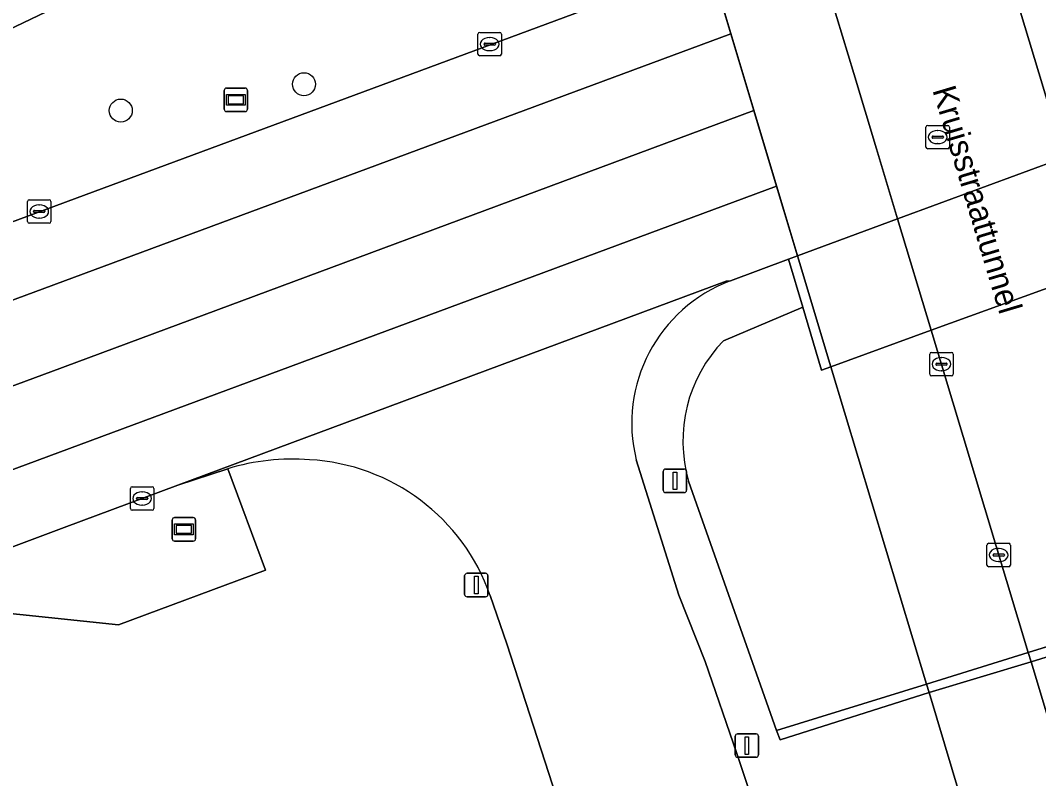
# Model space of a CAD drawing. Extents: x 160806 to 161707, y 383696 to 384148.
# Drawn here: x 161099.49 to 161142.86, y 383847.08 to 383879.38 of the extents above; entities that cross this region are included whole.
import ezdxf

# ---------------------------------------------------------------- set-up
doc = ezdxf.new("R2010")
doc.units = 0
for name, color, linetype in [('IMGEO_Berm_groen', 7, 'Continuous'), ('IMGEO_Boom', 7, 'Continuous'), ('IMGEO_Fietspad_gesloten', 7, 'Continuous'), ('IMGEO_Groenvoorziening', 7, 'Continuous'), ('IMGEO_Kolk', 7, 'Continuous'), ('IMGEO_Lichtmast', 7, 'Continuous'), ('IMGEO_Muur', 7, 'Continuous'), ('IMGEO_Openbare_ruimte_label', 7, 'Continuous'), ('IMGEO_Parkeervlak_halfverhard', 7, 'Continuous'), ('IMGEO_Rijbaan_lokaal_gesloten', 7, 'Continuous'), ('IMGEO_Rioolput', 7, 'Continuous'), ('IMGEO_Terreindeel_gesloten', 7, 'Continuous'), ('IMGEO_Tunneldeel', 7, 'Continuous'), ('IMGEO_Verkeersbordpaal', 7, 'Continuous'), ('IMGEO_Voetpad_open', 7, 'Continuous'), ('IMGEO_Wegwijzer', 7, 'Continuous')]:
    doc.layers.add(name, color=color, linetype=linetype)

msp = doc.modelspace()

# ---------------------------------------------------------------- linework, layer by layer
at = {"layer": 'IMGEO_Berm_groen'}
for points in [[(161087.876, 383866.621), (161128.848, 383881.822)], [(161101.252, 383880.057), (161097.638, 383878.338), (161096.217, 383877.724), (161094.845, 383877.209), (161070.968, 383868.293)], [(161108.335, 383860.281), (161106.205, 383859.577), (161101.356, 383857.78), (161078.73, 383849.295)], [(161079.101, 383847.887), (161096.474, 383854.38), (161103.677, 383853.631), (161109.937, 383855.961), (161108.335, 383860.281)]]:
    msp.add_lwpolyline(points, dxfattribs=at)
at = {"layer": 'IMGEO_Boom'}
for centre in [(161111.572, 383876.66), (161103.771, 383875.537)]:
    msp.add_circle(centre, 0.489, dxfattribs=at)
at = {"layer": 'IMGEO_Fietspad_gesloten'}
for points in [[(161138.282, 383866.176), (161145.381, 383868.752), (161143.943, 383873.537), (161143.043, 383876.531), (161142.082, 383879.729), (161141.127, 383882.908), (161140.189, 383886.03), (161139.898, 383886.998), (161139.762, 383887.449), (161132.666, 383884.829), (161132.802, 383884.376), (161133.097, 383883.398), (161134.025, 383880.315), (161134.987, 383877.121), (161135.955, 383873.904), (161136.85, 383870.932)], [(161145.381, 383868.752), (161138.282, 383866.176), (161142.416, 383852.446), (161147.686, 383854.079), (161147.449, 383854.857), (161145.358, 383861.789), (161146.034, 383866.359)], [(161150.124, 383846.082), (161147.804, 383853.693), (161147.686, 383854.079), (161142.416, 383852.446), (161142.534, 383852.055), (161144.827, 383844.441), (161145.8, 383841.21), (161146.837, 383837.764), (161147.656, 383835.045), (161147.77, 383834.67), (161153.099, 383836.327)]]:
    msp.add_lwpolyline(points, close=True, dxfattribs=at)
at = {"layer": 'IMGEO_Groenvoorziening'}
for points in [[(161129.436, 383865.731), (161132.81, 383867.162), (161132.21, 383869.205), (161129.731, 383868.28)], [(161134.004, 383864.624), (161133.615, 383864.483), (161132.81, 383867.162), (161129.436, 383865.731)], [(161127.952, 383859.751), (161131.695, 383849.124), (161138.086, 383851.104), (161134.004, 383864.624)], [(161125.724, 383860.653), (161127.533, 383854.899), (161128.653, 383852.066), (161130.01, 383848.147), (161131.736, 383842.961), (161135.037, 383841.409), (161140.315, 383843.044), (161140.482, 383843.096), (161138.194, 383850.745)], [(161138.194, 383850.745), (161131.856, 383848.736), (161131.695, 383849.124), (161127.952, 383859.751)]]:
    msp.add_lwpolyline(points, dxfattribs=at)
msp.add_lwpolyline([(161152.666, 383848.01), (161153.573, 383848.966), (161151.776, 383854.928), (161149.727, 383854.291), (161147.804, 383853.693), (161142.534, 383852.055), (161138.194, 383850.745), (161140.482, 383843.096), (161144.827, 383844.441), (161145.114, 383844.53), (161150.124, 383846.082), (161151.824, 383846.609), (161151.764, 383846.764), (161151.689, 383847.054), (161151.854, 383847.215)], close=True, dxfattribs=at)
for centre, radius, start, end in [((161131.996, 383862.224), 6.466, 110.5051, 194.0627), ((161133.83, 383861.466), 6.123, 135.8568, 196.2692), ((161133.83, 383861.466), 6.123, 135.8568, 196.2692)]:
    msp.add_arc(centre, radius, start, end, dxfattribs=at)
at = {"layer": 'IMGEO_Kolk'}
for p, q in [((161118.98, 383877.942), (161118.98, 383878.794)), ((161119.055, 383878.868), (161119.907, 383878.868)), ((161119.468, 383878.648), (161119.493, 383878.648)), ((161119.981, 383878.794), (161119.981, 383877.942)), ((161119.239, 383878.362), (161119.239, 383878.374)), ((161119.677, 383878.325), (161119.279, 383878.325)), ((161119.282, 383878.411), (161119.68, 383878.411)), ((161119.723, 383878.374), (161119.723, 383878.362)), ((161119.907, 383877.868), (161119.055, 383877.868)), ((161119.491, 383878.088), (161119.466, 383878.088)), ((161099.797, 383870.814), (161099.797, 383871.666)), ((161099.872, 383871.74), (161100.724, 383871.74)), ((161100.798, 383871.666), (161100.798, 383870.814)), ((161100.056, 383871.234), (161100.056, 383871.246)), ((161100.494, 383871.197), (161100.096, 383871.197)), ((161100.099, 383871.283), (161100.497, 383871.283)), ((161100.285, 383871.52), (161100.31, 383871.52)), ((161100.54, 383871.246), (161100.54, 383871.234)), ((161100.724, 383870.74), (161099.872, 383870.74)), ((161100.308, 383870.96), (161100.283, 383870.96)), ((161138.218, 383864.308), (161138.218, 383865.16)), ((161138.293, 383865.234), (161139.145, 383865.234)), ((161139.219, 383865.16), (161139.219, 383864.308)), ((161138.477, 383864.728), (161138.477, 383864.74)), ((161138.915, 383864.691), (161138.517, 383864.691)), ((161138.52, 383864.777), (161138.918, 383864.777)), ((161138.706, 383865.014), (161138.731, 383865.014)), ((161138.961, 383864.74), (161138.961, 383864.728)), ((161139.145, 383864.234), (161138.293, 383864.234)), ((161138.729, 383864.454), (161138.704, 383864.454)), ((161104.254, 383859.514), (161105.106, 383859.514)), ((161104.179, 383858.588), (161104.179, 383859.44)), ((161104.438, 383859.008), (161104.438, 383859.02)), ((161104.481, 383859.057), (161104.879, 383859.057)), ((161104.667, 383859.294), (161104.692, 383859.294)), ((161104.922, 383859.02), (161104.922, 383859.008)), ((161105.18, 383859.44), (161105.18, 383858.588)), ((161104.876, 383858.971), (161104.478, 383858.971)), ((161104.69, 383858.734), (161104.665, 383858.734)), ((161105.106, 383858.514), (161104.254, 383858.514)), ((161140.656, 383856.18), (161140.656, 383857.032)), ((161140.731, 383857.106), (161141.583, 383857.106)), ((161141.144, 383856.886), (161141.169, 383856.886)), ((161141.657, 383857.032), (161141.657, 383856.18)), ((161140.915, 383856.6), (161140.915, 383856.612)), ((161141.353, 383856.563), (161140.955, 383856.563)), ((161140.958, 383856.649), (161141.356, 383856.649)), ((161141.399, 383856.612), (161141.399, 383856.6)), ((161141.583, 383856.106), (161140.731, 383856.106)), ((161141.167, 383856.326), (161141.142, 383856.326))]:
    msp.add_line(p, q, dxfattribs=at)
for points in [[(161118.98, 383877.942), (161118.98, 383878.794)], [(161119.055, 383878.868), (161119.907, 383878.868)], [(161119.981, 383878.794), (161119.981, 383877.942)], [(161119.907, 383877.868), (161119.055, 383877.868)], [(161099.797, 383870.814), (161099.797, 383871.666)], [(161099.872, 383871.74), (161100.724, 383871.74)], [(161100.798, 383871.666), (161100.798, 383870.814)], [(161100.724, 383870.74), (161099.872, 383870.74)], [(161138.218, 383864.308), (161138.218, 383865.16)], [(161138.293, 383865.234), (161139.145, 383865.234)], [(161139.219, 383865.16), (161139.219, 383864.308)], [(161139.145, 383864.234), (161138.293, 383864.234)], [(161104.254, 383859.514), (161105.106, 383859.514)], [(161104.179, 383858.588), (161104.179, 383859.44)], [(161105.18, 383859.44), (161105.18, 383858.588)], [(161105.106, 383858.514), (161104.254, 383858.514)], [(161140.656, 383856.18), (161140.656, 383857.032)], [(161140.731, 383857.106), (161141.583, 383857.106)], [(161141.657, 383857.032), (161141.657, 383856.18)], [(161141.583, 383856.106), (161140.731, 383856.106)]]:
    msp.add_lwpolyline(points, dxfattribs=at)
for centre, radius, start, end in [((161119.057, 383878.792), 0.0765, 91.552, 178.448), ((161119.057, 383878.792), 0.0765, 91.552, 178.448), ((161119.905, 383878.792), 0.0765, 1.552, 88.448), ((161119.905, 383878.792), 0.0765, 1.552, 88.448), ((161119.279, 383878.371), 0.0403, 85.8775, 175.7526), ((161119.276, 383878.361), 0.0366, 178.938, 274.7102), ((161119.68, 383878.368), 0.043, 264.8664, 352.4533), ((161119.684, 383878.373), 0.0386, 1.7309, 96.639), ((161119.057, 383877.944), 0.0765, 181.552, 268.448), ((161119.057, 383877.944), 0.0765, 181.552, 268.448), ((161119.905, 383877.944), 0.0765, 271.552, 358.448), ((161119.905, 383877.944), 0.0765, 271.552, 358.448), ((161099.874, 383871.664), 0.0765, 91.552, 178.448), ((161099.874, 383871.664), 0.0765, 91.552, 178.448), ((161100.722, 383871.664), 0.0765, 1.552, 88.448), ((161100.722, 383871.664), 0.0765, 1.552, 88.448), ((161100.096, 383871.243), 0.0403, 85.8775, 175.7526), ((161100.093, 383871.233), 0.0366, 178.938, 274.7102), ((161100.497, 383871.24), 0.043, 264.8664, 352.4533), ((161100.501, 383871.245), 0.0386, 1.7309, 96.639), ((161099.874, 383870.816), 0.0765, 181.552, 268.448), ((161099.874, 383870.816), 0.0765, 181.552, 268.448), ((161100.722, 383870.816), 0.0765, 271.552, 358.448), ((161100.722, 383870.816), 0.0765, 271.552, 358.448), ((161138.295, 383865.158), 0.0765, 91.552, 178.448), ((161138.295, 383865.158), 0.0765, 91.552, 178.448), ((161139.143, 383865.158), 0.0765, 1.552, 88.448), ((161139.143, 383865.158), 0.0765, 1.552, 88.448), ((161138.517, 383864.737), 0.0403, 85.8775, 175.7526), ((161138.514, 383864.727), 0.0366, 178.938, 274.7102), ((161138.918, 383864.734), 0.043, 264.8664, 352.4533), ((161138.922, 383864.739), 0.0386, 1.7309, 96.639), ((161138.295, 383864.31), 0.0765, 181.552, 268.448), ((161138.295, 383864.31), 0.0765, 181.552, 268.448), ((161139.143, 383864.31), 0.0765, 271.552, 358.448), ((161139.143, 383864.31), 0.0765, 271.552, 358.448), ((161104.256, 383859.438), 0.0765, 91.552, 178.448), ((161104.256, 383859.438), 0.0765, 91.552, 178.448), ((161105.104, 383859.438), 0.0765, 1.552, 88.448), ((161105.104, 383859.438), 0.0765, 1.552, 88.448), ((161104.478, 383859.017), 0.0403, 85.8775, 175.7526), ((161104.883, 383859.019), 0.0386, 1.7309, 96.639), ((161104.256, 383858.59), 0.0765, 181.552, 268.448), ((161104.256, 383858.59), 0.0765, 181.552, 268.448), ((161104.475, 383859.007), 0.0366, 178.938, 274.7102), ((161104.879, 383859.014), 0.043, 264.8664, 352.4533), ((161105.104, 383858.59), 0.0765, 271.552, 358.448), ((161105.104, 383858.59), 0.0765, 271.552, 358.448), ((161140.733, 383857.03), 0.0765, 91.552, 178.448), ((161140.733, 383857.03), 0.0765, 91.552, 178.448), ((161141.581, 383857.03), 0.0765, 1.552, 88.448), ((161141.581, 383857.03), 0.0765, 1.552, 88.448), ((161140.955, 383856.609), 0.0403, 85.8775, 175.7526), ((161140.952, 383856.599), 0.0366, 178.938, 274.7102), ((161141.356, 383856.606), 0.043, 264.8664, 352.4533), ((161141.36, 383856.611), 0.0386, 1.7309, 96.639), ((161140.733, 383856.182), 0.0765, 181.552, 268.448), ((161140.733, 383856.182), 0.0765, 181.552, 268.448), ((161141.581, 383856.182), 0.0765, 271.552, 358.448), ((161141.581, 383856.182), 0.0765, 271.552, 358.448)]:
    msp.add_arc(centre, radius, start, end, dxfattribs=at)
for centre, major_axis, ratio, start_param, end_param in [((161119.467, 383878.368), (-0.387, 0.002), 0.722429, 4.712389, 7.853982), ((161119.492, 383878.368), (-0.39, 0.002), 0.717154, 1.570796, 4.712389), ((161100.284, 383871.24), (-0.387, 0.002), 0.722429, 4.712389, 7.853982), ((161100.309, 383871.24), (-0.39, 0.002), 0.717154, 1.570796, 4.712389), ((161138.705, 383864.734), (-0.387, 0.002), 0.722429, 4.712389, 7.853982), ((161138.73, 383864.734), (-0.39, 0.002), 0.717154, 1.570796, 4.712389), ((161104.666, 383859.014), (-0.387, 0.002), 0.722429, 4.712389, 7.853982), ((161104.691, 383859.014), (-0.39, 0.002), 0.717154, 1.570796, 4.712389), ((161141.143, 383856.606), (-0.387, 0.002), 0.722429, 4.712389, 7.853982), ((161141.168, 383856.606), (-0.39, 0.002), 0.717154, 1.570796, 4.712389)]:
    msp.add_ellipse(centre, major_axis=major_axis, ratio=ratio, start_param=start_param, end_param=end_param, dxfattribs=at)
at = {"layer": 'IMGEO_Lichtmast'}
for p, q in [((161129.938, 383848.088), (161129.938, 383848.888)), ((161129.938, 383848.888), (161129.938, 383848.088)), ((161130.038, 383848.988), (161130.828, 383848.988)), ((161130.828, 383848.988), (161130.038, 383848.988)), ((161130.928, 383848.888), (161130.928, 383848.088)), ((161130.928, 383848.088), (161130.928, 383848.888)), ((161130.828, 383847.988), (161130.038, 383847.988)), ((161130.038, 383847.988), (161130.828, 383847.988))]:
    msp.add_line(p, q, dxfattribs=at)
msp.add_lwpolyline([(161130.358, 383848.863), (161130.508, 383848.863), (161130.508, 383848.113), (161130.358, 383848.113), (161130.358, 383848.863)], dxfattribs=at)
for centre, start, end in [((161130.038, 383848.888), 90, 180), ((161130.038, 383848.888), 90, 180), ((161130.828, 383848.888), 0, 90), ((161130.828, 383848.888), 360, 90), ((161130.038, 383848.088), 180, 270), ((161130.038, 383848.088), 180, 270), ((161130.828, 383848.088), 270, 0), ((161130.828, 383848.088), 270, 0)]:
    msp.add_arc(centre, 0.1, start, end, dxfattribs=at)
at = {"layer": 'IMGEO_Muur'}
for points in [[(161132.588, 383869.346), (161132.21, 383869.205), (161132.81, 383867.162), (161133.615, 383864.483), (161134.004, 383864.624)], [(161147.804, 383853.693), (161149.727, 383854.291), (161151.776, 383854.928), (161151.661, 383855.311), (161149.611, 383854.676), (161147.686, 383854.079), (161142.416, 383852.446), (161138.086, 383851.104), (161138.194, 383850.745), (161142.534, 383852.055)], [(161138.194, 383850.745), (161138.086, 383851.104), (161131.695, 383849.124), (161131.856, 383848.736)]]:
    msp.add_lwpolyline(points, close=True, dxfattribs=at)
at = {"layer": 'IMGEO_Parkeervlak_halfverhard'}
for points in [[(161108.335, 383860.281), (161109.937, 383855.961), (161103.677, 383853.631), (161096.474, 383854.38), (161079.101, 383847.887)], [(161120.21, 383852.825), (161119.503, 383854.878)], [(161073.576, 383843.824), (161073.796, 383830.844), (161077.849, 383832.078), (161078.217, 383830.885), (161090.201, 383834.315), (161090.4, 383833.597), (161122.163, 383842.339), (161122.277, 383841.94), (161123.615, 383842.308), (161120.21, 383852.825)]]:
    msp.add_lwpolyline(points, dxfattribs=at)
for centre, radius, start, end in [((161111.08, 383851.302), 9.389, 85.5587, 106.9985), ((161111.328, 383852.014), 8.663, 19.3082, 86.8283)]:
    msp.add_arc(centre, radius, start, end, dxfattribs=at)
at = {"layer": 'IMGEO_Rijbaan_lokaal_gesloten'}
for points in [[(161144.172, 383880.216), (161143.232, 383883.37), (161142.214, 383886.781), (161140.189, 383886.03), (161133.097, 383883.398), (161128.848, 383881.822), (161129.754, 383878.799), (161130.73, 383875.543), (161131.695, 383872.323), (161132.588, 383869.346), (161136.85, 383870.932), (161143.943, 383873.537), (161145.945, 383874.273), (161145.116, 383877.053)], [(161054.975, 383847.445), (161068.088, 383852.305), (161100.785, 383864.404), (161130.73, 383875.543), (161129.754, 383878.799), (161070.422, 383856.806), (161066.684, 383855.364), (161053.934, 383850.623), (161048.71, 383848.68), (161010.322, 383834.458), (161000, 383830.636), (160965.623, 383817.907), (160966.768, 383814.836), (161001.838, 383827.792), (161009.318, 383830.547)], [(161131.695, 383872.323), (161130.73, 383875.543), (161100.785, 383864.404), (161068.088, 383852.305), (161054.975, 383847.445), (161009.318, 383830.547), (161001.838, 383827.792), (160966.768, 383814.836), (160967.931, 383811.718), (161000.642, 383823.738), (161029.952, 383834.573), (161050.221, 383842.097), (161054.918, 383843.967), (161058.494, 383845.391), (161059.41, 383845.762), (161062.999, 383847.001), (161070.515, 383849.722), (161085.394, 383855.134)]]:
    msp.add_lwpolyline(points, close=True, dxfattribs=at)
for points in [[(161129.754, 383878.799), (161128.848, 383881.822), (161087.876, 383866.621)], [(161070.968, 383868.293), (161094.845, 383877.209), (161096.217, 383877.724), (161097.638, 383878.338), (161101.252, 383880.057)], [(161070.422, 383856.806), (161129.754, 383878.799)], [(161129.555, 383868.265), (161129.731, 383868.28), (161132.21, 383869.205), (161132.588, 383869.346), (161131.695, 383872.323), (161085.394, 383855.134), (161070.515, 383849.722), (161062.999, 383847.001), (161059.41, 383845.762)], [(161078.73, 383849.295), (161101.356, 383857.78), (161106.205, 383859.577), (161129.555, 383868.265)], [(161129.731, 383868.28), (161129.555, 383868.265), (161106.205, 383859.577), (161108.335, 383860.281)], [(161127.533, 383854.899), (161125.724, 383860.653)], [(161119.503, 383854.878), (161120.21, 383852.825), (161123.615, 383842.308), (161124.928, 383838.252), (161132.513, 383840.627), (161131.736, 383842.961), (161130.01, 383848.147), (161128.653, 383852.066), (161127.533, 383854.899)]]:
    msp.add_lwpolyline(points, dxfattribs=at)
for centre, radius, start, end in [((161131.996, 383862.224), 6.466, 110.5051, 194.0627), ((161111.08, 383851.302), 9.389, 85.5587, 106.9985), ((161111.328, 383852.014), 8.663, 19.3082, 86.8283)]:
    msp.add_arc(centre, radius, start, end, dxfattribs=at)
at = {"layer": 'IMGEO_Rioolput'}
for p, q in [((161138.058, 383873.981), (161138.058, 383874.833)), ((161138.133, 383874.907), (161138.985, 383874.907)), ((161138.546, 383874.687), (161138.571, 383874.687)), ((161139.059, 383874.833), (161139.059, 383873.981)), ((161138.317, 383874.401), (161138.317, 383874.413)), ((161138.755, 383874.364), (161138.357, 383874.364)), ((161138.36, 383874.45), (161138.758, 383874.45)), ((161138.801, 383874.413), (161138.801, 383874.401)), ((161138.985, 383873.907), (161138.133, 383873.907)), ((161138.569, 383874.127), (161138.544, 383874.127))]:
    msp.add_line(p, q, dxfattribs=at)
for points in [[(161138.058, 383873.981), (161138.058, 383874.833)], [(161138.133, 383874.907), (161138.985, 383874.907)], [(161139.059, 383874.833), (161139.059, 383873.981)], [(161138.985, 383873.907), (161138.133, 383873.907)]]:
    msp.add_lwpolyline(points, dxfattribs=at)
for centre, radius, start, end in [((161138.135, 383874.831), 0.0765, 91.552, 178.448), ((161138.135, 383874.831), 0.0765, 91.552, 178.448), ((161138.983, 383874.831), 0.0765, 1.552, 88.448), ((161138.983, 383874.831), 0.0765, 1.552, 88.448), ((161138.357, 383874.41), 0.0403, 85.8775, 175.7526), ((161138.354, 383874.4), 0.0366, 178.938, 274.7102), ((161138.758, 383874.407), 0.043, 264.8664, 352.4533), ((161138.762, 383874.412), 0.0386, 1.7309, 96.639), ((161138.135, 383873.983), 0.0765, 181.552, 268.448), ((161138.135, 383873.983), 0.0765, 181.552, 268.448), ((161138.983, 383873.983), 0.0765, 271.552, 358.448), ((161138.983, 383873.983), 0.0765, 271.552, 358.448)]:
    msp.add_arc(centre, radius, start, end, dxfattribs=at)
for centre, major_axis, ratio, start_param, end_param in [((161138.545, 383874.407), (-0.387, 0.002), 0.722429, 4.712389, 7.853982), ((161138.57, 383874.407), (-0.39, 0.002), 0.717154, 1.570796, 4.712389)]:
    msp.add_ellipse(centre, major_axis=major_axis, ratio=ratio, start_param=start_param, end_param=end_param, dxfattribs=at)
at = {"layer": 'IMGEO_Terreindeel_gesloten'}
msp.add_lwpolyline([(161145.945, 383874.273), (161143.943, 383873.537), (161136.85, 383870.932), (161132.588, 383869.346), (161134.004, 383864.624), (161138.282, 383866.176), (161145.381, 383868.752), (161147.376, 383869.475)], close=True, dxfattribs=at)
at = {"layer": 'IMGEO_Tunneldeel'}
for points in [[(161142.214, 383886.781), (161141.926, 383887.748), (161141.791, 383888.198), (161139.762, 383887.449), (161132.666, 383884.829), (161128.417, 383883.26), (161128.299, 383883.216), (161128.402, 383882.878), (161128.519, 383882.921), (161128.553, 383882.806), (161128.848, 383881.822), (161132.588, 383869.346), (161134.004, 383864.624), (161138.282, 383866.176), (161145.381, 383868.752), (161147.376, 383869.475), (161145.945, 383874.273)], [(161154.024, 383847.47), (161153.895, 383847.899), (161153.748, 383848.385), (161153.573, 383848.966), (161151.776, 383854.928), (161151.661, 383855.311), (161149.611, 383854.676), (161142.416, 383852.446), (161138.086, 383851.104), (161138.194, 383850.745), (161140.482, 383843.096), (161142.482, 383836.411), (161143.295, 383833.692), (161143.408, 383833.314), (161147.77, 383834.67), (161154.96, 383836.906), (161157.016, 383837.543), (161156.904, 383837.916), (161156.084, 383840.634)]]:
    msp.add_lwpolyline(points, close=True, dxfattribs=at)
at = {"layer": 'IMGEO_Verkeersbordpaal'}
for p, q in [((161126.873, 383859.366), (161126.873, 383860.166)), ((161126.873, 383860.166), (161126.873, 383859.366)), ((161126.973, 383860.266), (161127.763, 383860.266)), ((161127.763, 383860.266), (161126.973, 383860.266)), ((161127.863, 383860.166), (161127.863, 383859.366)), ((161127.863, 383859.366), (161127.863, 383860.166)), ((161127.763, 383859.266), (161126.973, 383859.266)), ((161126.973, 383859.266), (161127.763, 383859.266)), ((161118.414, 383854.926), (161118.414, 383855.726)), ((161118.414, 383855.726), (161118.414, 383854.926)), ((161118.514, 383855.826), (161119.304, 383855.826)), ((161119.304, 383855.826), (161118.514, 383855.826)), ((161119.404, 383855.726), (161119.404, 383854.926)), ((161119.404, 383854.926), (161119.404, 383855.726)), ((161119.304, 383854.826), (161118.514, 383854.826)), ((161118.514, 383854.826), (161119.304, 383854.826))]:
    msp.add_line(p, q, dxfattribs=at)
for points in [[(161127.293, 383860.141), (161127.443, 383860.141), (161127.443, 383859.391), (161127.293, 383859.391), (161127.293, 383860.141)], [(161118.834, 383855.701), (161118.984, 383855.701), (161118.984, 383854.951), (161118.834, 383854.951), (161118.834, 383855.701)]]:
    msp.add_lwpolyline(points, dxfattribs=at)
for centre, start, end in [((161126.973, 383860.166), 90, 180), ((161126.973, 383860.166), 90, 180), ((161127.763, 383860.166), 0, 90), ((161127.763, 383860.166), 360, 90), ((161126.973, 383859.366), 180, 270), ((161126.973, 383859.366), 180, 270), ((161127.763, 383859.366), 270, 0), ((161127.763, 383859.366), 270, 0), ((161118.514, 383855.726), 90, 180), ((161118.514, 383855.726), 90, 180), ((161119.304, 383855.726), 0, 90), ((161119.304, 383855.726), 360, 90), ((161118.514, 383854.926), 180, 270), ((161118.514, 383854.926), 180, 270), ((161119.304, 383854.926), 270, 0), ((161119.304, 383854.926), 270, 0)]:
    msp.add_arc(centre, 0.1, start, end, dxfattribs=at)
at = {"layer": 'IMGEO_Voetpad_open'}
for points in [[(161145.381, 383868.752), (161147.376, 383869.475), (161145.945, 383874.273), (161142.214, 383886.781), (161141.926, 383887.748), (161141.791, 383888.198), (161139.762, 383887.449), (161139.898, 383886.998), (161140.189, 383886.03), (161141.127, 383882.908), (161142.082, 383879.729), (161143.043, 383876.531), (161143.943, 383873.537)], [(161134.004, 383864.624), (161138.282, 383866.176), (161136.85, 383870.932), (161135.955, 383873.904), (161134.987, 383877.121), (161134.025, 383880.315), (161133.097, 383883.398), (161132.802, 383884.376), (161132.666, 383884.829), (161128.417, 383883.26), (161128.299, 383883.216), (161128.402, 383882.878), (161128.519, 383882.921), (161128.553, 383882.806), (161128.848, 383881.822), (161132.588, 383869.346)], [(161138.086, 383851.104), (161142.416, 383852.446), (161138.282, 383866.176), (161134.004, 383864.624)], [(161143.408, 383833.314), (161147.77, 383834.67), (161147.656, 383835.045), (161146.837, 383837.764), (161145.8, 383841.21), (161144.827, 383844.441), (161142.534, 383852.055), (161142.416, 383852.446), (161138.086, 383851.104), (161138.194, 383850.745), (161140.482, 383843.096), (161142.482, 383836.411), (161143.295, 383833.692)]]:
    msp.add_lwpolyline(points, close=True, dxfattribs=at)
at = {"layer": 'IMGEO_Wegwijzer'}
for p, q in [((161108.175, 383875.592), (161108.175, 383876.392)), ((161108.175, 383876.392), (161108.175, 383875.592)), ((161108.275, 383876.492), (161109.065, 383876.492)), ((161109.065, 383876.492), (161108.275, 383876.492)), ((161109.165, 383876.392), (161109.165, 383875.592)), ((161109.165, 383875.592), (161109.165, 383876.392)), ((161109.065, 383875.492), (161108.275, 383875.492)), ((161108.275, 383875.492), (161109.065, 383875.492)), ((161106.063, 383858.198), (161106.853, 383858.198)), ((161106.853, 383858.198), (161106.063, 383858.198)), ((161105.963, 383857.298), (161105.963, 383858.098)), ((161105.963, 383858.098), (161105.963, 383857.298)), ((161106.953, 383858.098), (161106.953, 383857.298)), ((161106.953, 383857.298), (161106.953, 383858.098)), ((161106.853, 383857.198), (161106.063, 383857.198)), ((161106.063, 383857.198), (161106.853, 383857.198))]:
    msp.add_line(p, q, dxfattribs=at)
for points in [[(161108.276, 383876.224), (161109.064, 383876.224), (161109.064, 383875.76), (161108.276, 383875.76), (161108.276, 383876.224)], [(161108.341, 383876.159), (161108.341, 383875.825), (161108.999, 383875.825), (161108.999, 383876.159), (161108.341, 383876.159)], [(161106.064, 383857.93), (161106.852, 383857.93), (161106.852, 383857.466), (161106.064, 383857.466), (161106.064, 383857.93)], [(161106.129, 383857.865), (161106.129, 383857.531), (161106.787, 383857.531), (161106.787, 383857.865), (161106.129, 383857.865)]]:
    msp.add_lwpolyline(points, dxfattribs=at)
for centre, start, end in [((161108.275, 383876.392), 90, 180), ((161108.275, 383876.392), 90, 180), ((161109.065, 383876.392), 0, 90), ((161109.065, 383876.392), 360, 90), ((161108.275, 383875.592), 180, 270), ((161108.275, 383875.592), 180, 270), ((161109.065, 383875.592), 270, 0), ((161109.065, 383875.592), 270, 0), ((161106.063, 383858.098), 90, 180), ((161106.063, 383858.098), 90, 180), ((161106.853, 383858.098), 0, 90), ((161106.853, 383858.098), 360, 90), ((161106.063, 383857.298), 180, 270), ((161106.063, 383857.298), 180, 270), ((161106.853, 383857.298), 270, 0), ((161106.853, 383857.298), 270, 0)]:
    msp.add_arc(centre, 0.1, start, end, dxfattribs=at)

# ---------------------------------------------------------------- texts
at = {"layer": 'IMGEO_Openbare_ruimte_label'}
msp.add_text('Kruisstraattunnel', height=1, rotation=286.6773, dxfattribs=at).set_placement((161138.325, 383876.415))

doc.saveas('drawing.dxf')
